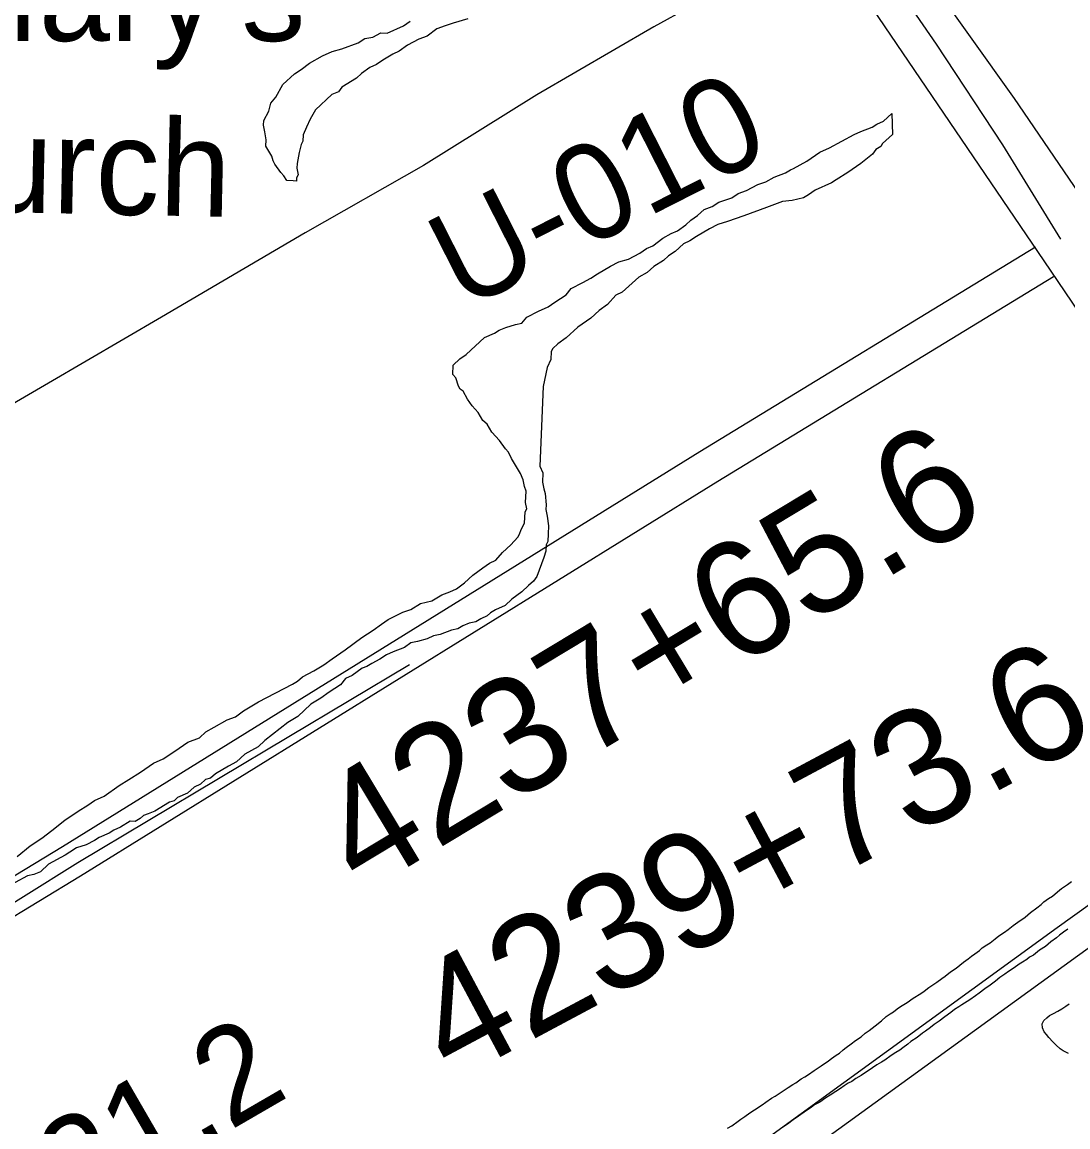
# Model space of a CAD drawing. Extents: x 3297753 to 3335611, y 652252 to 677623.
# Drawn here: x 3307391 to 3308297, y 669630 to 670586 of the extents above; entities that cross this region are included whole.
import ezdxf

# ---------------------------------------------------------------- set-up
doc = ezdxf.new("R2010")
doc.units = 0
for name, color, linetype in [('V-DTCH-CNTR', 7, 'Continuous'), ('V-LEVE-TOET', 7, 'Continuous'), ('V-RIVR-EDGE', 7, 'Continuous'), ('V-RIVR-RANG-IDEN', 7, 'Continuous'), ('V-ROAD-CNTR', 7, 'Continuous'), ('V-SITE-OTLN-IDEN', 7, 'Continuous'), ('V-SITE-VEGE', 7, 'Continuous'), ('V-SURV-IDEN', 7, 'Continuous'), ('V-TOPO-SHOR', 7, 'Continuous')]:
    doc.layers.add(name, color=color, linetype=linetype)

msp = doc.modelspace()

# ---------------------------------------------------------------- linework, layer by layer
at = {"layer": 'V-DTCH-CNTR'}
msp.add_lwpolyline([(3306851.89, 669500.8), (3306913.26, 669538.63), (3307005.87, 669594.48), (3307103.25, 669652.46), (3307138.08, 669673.72), (3307161.6, 669688.08), (3307298.09, 669770.19), (3307439.54, 669858.54), (3307622.29, 669967.41), (3307726.89, 670029.78)], dxfattribs=at)
at = {"layer": 'V-LEVE-TOET'}
msp.add_lwpolyline([(3308133.21, 670684.14), (3308250.51, 670519.66), (3308374.97, 670337.24), (3308533.16, 670097.88), (3308603.72, 669995.31), (3308676.85, 669890.86), (3308746.98, 669798.88), (3308783.09, 669756.81), (3308822.07, 669719.91), (3308908.96, 669649.25), (3309055.84, 669538.15), (3309202.86, 669430.58), (3309382.89, 669290.76), (3309531.09, 669190.18), (3309660.89, 669092.14), (3309690.67, 669067.09), (3309712.65, 669045.01), (3309817.76, 668967.41), (3309910.78, 668895.61), (3309933.41, 668877.39), (3310042.12, 668792.22), (3310236.32, 668633.29)], dxfattribs=at)
at = {"layer": 'V-RIVR-EDGE'}
msp.add_spline([(3307850.62, 675821), (3307850.75, 675819.26), (3307852.36, 675798.53), (3307852.34, 675791.07), (3307856.9, 675791.47), (3307860.2, 675784), (3307858.08, 675766.6), (3307858.03, 675745.87), (3307859.68, 675743.8), (3307863.41, 675742.96), (3307863.4, 675739.64), (3307862.94, 675720.99), (3307866.19, 675694.04), (3307864.47, 675668.35), (3307864.85, 675653.43), (3307866.04, 675632.29), (3307865.98, 675608.25), (3307860.93, 675578), (3307855.03, 675536.15), (3307852.01, 675490.98), (3307848.61, 675457.42), (3307845.62, 675420.95), (3307843.09, 675401.89), (3307841.81, 675387.8), (3307842.17, 675364.59), (3307841.69, 675337.23), (3307844.13, 675320.65), (3307845.74, 675299.92), (3307848.96, 675263.02), (3307851.37, 675230.27), (3307851.72, 675204.99), (3307854.14, 675179.28), (3307856.98, 675153.99), (3307856.53, 675138.24), (3307855.69, 675135.76), (3307856.07, 675118.35), (3307855.63, 675111.72), (3307854.35, 675095.97), (3307852.65, 675077.74), (3307852.18, 675054.11), (3307855.44, 675031.72), (3307862.38, 674991.5), (3307864.8, 674962.48), (3307868.44, 674926), (3307870.05, 674906.1), (3307872.46, 674875.01), (3307874.08, 674859.25), (3307876.52, 674843.5), (3307878.94, 674816.13), (3307882.53, 674757.68), (3307886.15, 674712.5), (3307885.71, 674704.21), (3307884.45, 674697.99), (3307884.44, 674691.78), (3307887.31, 674680.16), (3307887.28, 674668.97), (3307887.26, 674658.2), (3307885.58, 674651.15), (3307881.01, 674644.12), (3307881, 674639.97), (3307886.35, 674626.28), (3307890.03, 674605.55), (3307895.77, 674578.59), (3307899.43, 674550.81), (3307909.27, 674510.58), (3307914.59, 674481.97), (3307918.25, 674453.78), (3307918.22, 674440.51), (3307919.86, 674433.88), (3307927.3, 674423.08), (3307927.28, 674417.7), (3307927.25, 674404.02), (3307928.48, 674400.28), (3307931.78, 674393.23), (3307935.06, 674376.64), (3307944.54, 674357.55), (3307954.85, 674337.22), (3307963.92, 674316.06), (3307975.42, 674271.68), (3307986.49, 674225.23), (3308000.06, 674178.77), (3308007.44, 674148.91), (3308015.22, 674108.27), (3308020.53, 674078.42), (3308024.25, 674072.19), (3308025.04, 674059.34), (3308025.41, 674039.44), (3308027.79, 673997.16), (3308030.63, 673971.46), (3308027.69, 673955.3), (3308027.24, 673943.28), (3308027.64, 673935.82), (3308029.69, 673925.45), (3308035.46, 673911.76), (3308035.42, 673899.32), (3308034.12, 673873.21), (3308036.13, 673851.24), (3308038.54, 673818.91), (3308040.98, 673799), (3308046.76, 673788.21), (3308050.46, 673778.26), (3308048.79, 673772.46), (3308048.76, 673761.27), (3308053.68, 673740.53), (3308060.66, 673711.09), (3308069.7, 673678.73), (3308069.66, 673665.06), (3308067.15, 673653.46), (3308067.55, 673650.14), (3308072.94, 673649.3), (3308077.91, 673648.87), (3308079.98, 673646.38), (3308086.52, 673608.64), (3308091.84, 673582.1), (3308104.58, 673536.48), (3308114.83, 673495), (3308121.38, 673461), (3308123.83, 673446.07), (3308127.95, 673436.12), (3308140.31, 673406.24), (3308148.95, 673377.21), (3308153.04, 673357.72), (3308158.34, 673321.23), (3308169, 673273.12), (3308189.1, 673188.1), (3308196.88, 673150.37), (3308207.96, 673103.92), (3308212.04, 673079.45), (3308214.06, 673059.97), (3308216.51, 673045.04), (3308218.98, 673035.91), (3308226, 673025.53), (3308228.46, 673015.99), (3308228.43, 673002.32), (3308230.49, 672996.92), (3308235.04, 672992.77), (3308235.02, 672984.48), (3308237.47, 672972.87), (3308241.99, 672953.37), (3308247.32, 672933.05), (3308253.9, 672910.65), (3308257.61, 672901.53), (3308263.8, 672890.32), (3308276.17, 672865), (3308277.39, 672856.3), (3308278.62, 672850.08), (3308283.16, 672844.26), (3308286.05, 672839.7), (3308286.04, 672832.24), (3308285.59, 672818.97), (3308288.47, 672812.33), (3308293.83, 672800.3), (3308303.72, 672777.89), (3308309.9, 672762.54), (3308316.07, 672743.05), (3308316.44, 672725.64), (3308318.1, 672723.15), (3308323.06, 672717.33), (3308327.59, 672706.13), (3308331.69, 672690.37), (3308330.84, 672679.6), (3308330.4, 672672.14), (3308332.46, 672667.16), (3308337.42, 672658.44), (3308343.59, 672642.67), (3308347.7, 672625.26), (3308355.91, 672595.39), (3308355.89, 672584.62), (3308357.53, 672579.64), (3308362.07, 672570.92), (3308366.61, 672563.45), (3308376.07, 672534), (3308399.56, 672478.4), (3308411.51, 672452.67), (3308418.52, 672435.25), (3308421.79, 672418.66), (3308423.01, 672409.95), (3308425.49, 672403.73), (3308428.79, 672397.5), (3308430.01, 672387.55), (3308434.95, 672375.52), (3308444.41, 672344.83), (3308450.58, 672326.99), (3308456.78, 672320.76), (3308459.66, 672312.87), (3308465.4, 672287.99), (3308467.43, 672268.09), (3308473.18, 672249.01), (3308476.05, 672236.57), (3308485.95, 672214.16), (3308490.05, 672198.81), (3308495.86, 672201.7), (3308496.67, 672193), (3308499.08, 672161.9), (3308505.23, 672134.53), (3308513.87, 672107.57), (3308522.52, 672084.75), (3308527.9, 672082.25), (3308536.2, 672087.2), (3308540.76, 672086.78), (3308539.51, 672083.88), (3308535.76, 672077.67), (3308534.91, 672067.73), (3308534.47, 672059.44), (3308531.96, 672050.74), (3308533.2, 672047.42), (3308536.91, 672037.88), (3308550.93, 672008.42), (3308564.93, 671974.39), (3308569.87, 671959.46), (3308576.49, 671954.88), (3308585.14, 671932.48), (3308595.86, 671910.49), (3308604.94, 671895.13), (3308605.76, 671888.49), (3308607.82, 671885.17), (3308610.71, 671881.02), (3308616.47, 671862.77), (3308627.6, 671838.7), (3308640.39, 671816.29), (3308660.99, 671765.26), (3308672.95, 671740.77), (3308685.32, 671715.46), (3308698.53, 671692.21), (3308700.17, 671685.58), (3308711.29, 671658.19), (3308728.21, 671627.9), (3308743.07, 671602.99), (3308758.34, 671575.6), (3308771.97, 671554.84), (3308775.27, 671548.61), (3308783.11, 671536.16), (3308790.54, 671522.88), (3308793.43, 671519.55), (3308797.16, 671517.06), (3308801.29, 671511.24), (3308803.76, 671502.95), (3308810.8, 671502.1), (3308815.77, 671499.19), (3308833.53, 671474.28), (3308845.09, 671458.5), (3308857.08, 671443.55), (3308870.72, 671429.01), (3308882.71, 671418.61), (3308908.77, 671397), (3308930.27, 671375.39), (3308944.33, 671361.26), (3308952.58, 671346.74), (3308960.43, 671336.77), (3308966.22, 671331.78), (3308972.85, 671328.86), (3308985.64, 671307.28), (3309001.75, 671282.37), (3309010.84, 671271.57), (3309010.83, 671268.25), (3309008.34, 671266.19), (3309011.64, 671262.03), (3309018.66, 671250.83), (3309024.85, 671237.13), (3309035.15, 671212.24), (3309059.5, 671169.07), (3309066.5, 671150.82), (3309067.71, 671140.45), (3309071.85, 671135.88), (3309077.22, 671128.41), (3309078.45, 671123.02), (3309078.43, 671117.63), (3309082.15, 671111.4), (3309089.15, 671092.73), (3309098.63, 671073.23), (3309111.41, 671045.01), (3309116.36, 671032.15), (3309123.35, 671011), (3309128.7, 670995.65), (3309133.23, 670984.86), (3309143.97, 670967.42), (3309159.66, 670945.42), (3309169.17, 670933.37), (3309181.99, 670924.22), (3309188.19, 670917.16), (3309197.69, 670902.22), (3309217.1, 670874.81), (3309231.57, 670859.03), (3309239.82, 670845.33), (3309244.79, 670840.76), (3309252.23, 670835.35), (3309260.51, 670831.18), (3309275.4, 670817.06), (3309282.43, 670810.41), (3309290.69, 670800.02), (3309303.1, 670788.39), (3309315.92, 670775.51), (3309335.34, 670751), (3309344.42, 670736.47), (3309351.03, 670726.51), (3309360.13, 670721.51), (3309375.84, 670704.9), (3309390.72, 670688.69), (3309403.11, 670668.77), (3309415.49, 670646.77), (3309426.65, 670635.14), (3309442.78, 670618.52), (3309454.34, 670603.15), (3309462.18, 670588.63), (3309470.85, 670575.34), (3309476.63, 670563.31), (3309487.39, 670558.31), (3309488.62, 670554.57), (3309489.44, 670550.84), (3309494.82, 670544.2), (3309506.81, 670533.39), (3309523.77, 670518.84), (3309529.95, 670505.98), (3309538.6, 670484.82), (3309549.72, 670453.7), (3309551.35, 670440.85), (3309555.47, 670430.89), (3309568.67, 670408.89), (3309577.35, 670396.02), (3309581.47, 670386.48), (3309581.46, 670383.16), (3309578.55, 670379.85), (3309576.88, 670374.88), (3309582.24, 670364.09), (3309594.61, 670336.71), (3309604.49, 670308.91), (3309606.94, 670296.06), (3309614.38, 670284.85), (3309627.18, 670266.99), (3309635.46, 670261.59), (3309639.18, 670259.92), (3309638.74, 670249.97), (3309639.54, 670236.29), (3309641.18, 670228), (3309644.89, 670221.36), (3309656.46, 670208.06), (3309664.31, 670195.61), (3309663.46, 670188.15), (3309663.84, 670176.13), (3309667.96, 670166.17), (3309673.34, 670159.94), (3309684.07, 670142.92), (3309690.66, 670126.33), (3309700.14, 670102.68), (3309716.65, 670076.52)], degree=3, dxfattribs=at)
at = {"layer": 'V-ROAD-CNTR'}
for points in [[(3307339.14, 672310.87), (3307407.41, 672029.86), (3307476.95, 671732.57), (3307511.07, 671600.1), (3307529.82, 671540.23), (3307554.17, 671481.54), (3307565.65, 671454.66), (3307628.51, 671339.43), (3307687.48, 671244.51), (3307819.52, 671049.73), (3308010.54, 670769.93), (3308276.08, 670379.16), (3308519.64, 670019.78), (3308575.25, 669936.41), (3308626.7, 669864.47), (3308662.44, 669815.55), (3308701.66, 669766.43), (3308749.57, 669726.83), (3308879.73, 669615.8), (3309312.15, 669283.51), (3309781.29, 668929.63), (3310172.08, 668625.19)], [(3308268.94, 670390.98), (3307978.15, 670213.72), (3307426.28, 669872.11), (3306771.84, 669474.94)], [(3308284.55, 670365.37), (3307993.85, 670188.16), (3307441.96, 669846.54), (3306828.11, 669473.99)], [(3308552.14, 669971.42), (3308505.63, 669941.31), (3308470.59, 669919.23), (3308429.58, 669897.99), (3308390.61, 669875.75), (3308287.73, 669801.85), (3307991.97, 669587.42), (3307744.65, 669410.84)], [(3308568.45, 669946.24), (3308521.78, 669916.02), (3308485.5, 669893.17), (3308443.92, 669871.63), (3308406.84, 669850.47), (3308305.29, 669777.52), (3308009.49, 669563.07), (3307762.08, 669386.42)]]:
    msp.add_lwpolyline(points, dxfattribs=at)
at = {"layer": 'V-SITE-VEGE'}
for points in [[(3307777.26, 670588.54), (3307764.66, 670584.92), (3307757.64, 670582.45), (3307750.62, 670579.98), (3307742.04, 670573.43), (3307735.03, 670570.96), (3307725.13, 670565.85), (3307717.99, 670560.62), (3307712.35, 670558.09), (3307703.84, 670552.92), (3307698.14, 670549.01), (3307692.5, 670546.48), (3307685.36, 670541.26), (3307681.04, 670537.29), (3307668.27, 670529.53), (3307665.33, 670525.51), (3307659.69, 670522.98), (3307645.3, 670509.76), (3307640.81, 670501.65), (3307637.75, 670494.86), (3307634.7, 670488.08), (3307634.47, 670482.56), (3307632.97, 670479.86), (3307631.3, 670473.01), (3307629.51, 670463.41), (3307629.33, 670459.26), (3307630.48, 670453.69), (3307628.98, 670450.98), (3307628.87, 670448.22), (3307626.11, 670448.34), (3307620.58, 670448.57), (3307618, 670452.83), (3307615.35, 670455.71), (3307610.12, 670462.84), (3307608.86, 670465.66), (3307607.65, 670469.86), (3307602.48, 670478.38), (3307602.72, 670483.9), (3307601.63, 670490.87), (3307600.48, 670496.45), (3307600.66, 670500.59), (3307605.15, 670508.7), (3307606.82, 670515.54), (3307611.2, 670520.89), (3307617.19, 670531.7), (3307627.26, 670540.95), (3307632.96, 670544.86), (3307640.1, 670550.09), (3307651.43, 670556.53), (3307659.89, 670560.32), (3307668.29, 670562.73), (3307682.33, 670567.66), (3307688.03, 670571.57), (3307694.99, 670572.66), (3307702.07, 670576.51), (3307707.59, 670576.28), (3307721.69, 670582.59), (3307727.39, 670586.5)], [(3308117.52, 670491.14), (3308127.36, 670494.87), (3308131.62, 670497.45), (3308137.25, 670499.98), (3308144.45, 670506.59), (3308145.07, 670488.58), (3308142.19, 670485.94), (3308136.44, 670480.65), (3308134.94, 670477.95), (3308130.68, 670475.36), (3308127.74, 670471.34), (3308117.72, 670463.47), (3308106.33, 670455.65), (3308096.38, 670449.16), (3308092.12, 670446.57), (3308078.02, 670440.26), (3308072.32, 670436.35), (3308068.06, 670433.76), (3308058.28, 670431.41), (3308049.94, 670430.38), (3308035.9, 670425.44), (3308016.22, 670417.98), (3308002.18, 670413.04), (3307993.78, 670410.63), (3307986.7, 670406.78), (3307975.37, 670400.34), (3307969.67, 670396.44), (3307964.03, 670393.91), (3307956.83, 670387.3), (3307951.13, 670383.39), (3307946.82, 670379.43), (3307938.3, 670374.26), (3307932.54, 670368.97)], [(3307576.02, 669984.37), (3307583.16, 669989.6), (3307595.93, 669997.36), (3307625.62, 670012.7), (3307629.88, 670015.28), (3307634.2, 670019.25), (3307644.1, 670024.36), (3307652.61, 670029.53), (3307659.75, 670034.76), (3307671.15, 670042.58), (3307685.42, 670053.04), (3307695.38, 670059.53), (3307702.52, 670064.76), (3307708.21, 670068.67), (3307720.93, 670075.05), (3307727.95, 670077.51), (3307736.47, 670082.68), (3307746.25, 670085.04), (3307754.77, 670090.21), (3307761.79, 670092.67), (3307767.43, 670095.2), (3307774.56, 670100.43), (3307781.76, 670107.05), (3307790.33, 670113.59), (3307796.03, 670117.5), (3307801.67, 670120.03), (3307807.48, 670126.7), (3307814.68, 670133.31), (3307820.5, 670139.98), (3307821.99, 670142.68), (3307823.55, 670146.76), (3307826.54, 670152.17), (3307826.95, 670161.83), (3307828.45, 670164.54), (3307827.31, 670170.12), (3307827.71, 670179.78), (3307826.51, 670183.98), (3307825.36, 670189.57), (3307822.83, 670195.2), (3307815.08, 670207.98), (3307812.55, 670213.62), (3307809.91, 670216.49), (3307804.68, 670223.63), (3307798.07, 670230.83), (3307794.22, 670237.91), (3307790.19, 670240.84), (3307786.34, 670247.92), (3307781.06, 670253.68), (3307777.15, 670259.38), (3307773.3, 670266.45), (3307770.6, 670267.95), (3307769.33, 670270.77), (3307766.86, 670277.79), (3307764.22, 670280.67), (3307764.57, 670288.95), (3307770.33, 670294.24), (3307776.02, 670298.15), (3307791.85, 670312.69), (3307800.31, 670316.48), (3307804.57, 670319.07), (3307810.21, 670321.59), (3307818.61, 670324), (3307824.19, 670325.15), (3307828.57, 670330.5), (3307838.46, 670335.61), (3307846.93, 670339.4), (3307852.62, 670343.31), (3307862.58, 670349.8), (3307866.96, 670355.15), (3307876.85, 670360.26), (3307883.93, 670364.11), (3307889.63, 670368.02), (3307900.97, 670374.45), (3307908.04, 670378.3), (3307916.45, 670380.71), (3307926.34, 670385.83), (3307932.04, 670389.73), (3307937.68, 670392.26), (3307946.25, 670398.82), (3307953.33, 670402.66), (3307958.97, 670405.19), (3307966.11, 670410.42), (3307970.43, 670414.39), (3307976.12, 670418.29), (3307981.88, 670423.58), (3307988.9, 670426.05), (3307994.6, 670429.96), (3308005.82, 670433.63), (3308011.52, 670437.54), (3308018.54, 670440.01), (3308028.44, 670445.12), (3308035.45, 670447.59), (3308042.53, 670451.44), (3308052.37, 670455.17), (3308056.63, 670457.76), (3308059.45, 670459.02), (3308070.79, 670465.45), (3308082.18, 670473.27), (3308090.64, 670477.06), (3308111.88, 670488.61), (3308117.52, 670491.14)], [(3307932.54, 670368.97), (3307925.46, 670365.11), (3307911.08, 670351.9), (3307905.44, 670349.37), (3307898.18, 670341.38), (3307891.04, 670336.15), (3307883.85, 670329.54), (3307872.45, 670321.72), (3307862.38, 670312.47), (3307855.24, 670307.24), (3307850.93, 670303.27), (3307849.43, 670300.57), (3307849.14, 670293.67), (3307846.08, 670286.88), (3307842.62, 670270.43), (3307839.7, 670201.4), (3307842.22, 670195.76), (3307841.87, 670187.48), (3307843.02, 670181.9), (3307844.22, 670177.7), (3307845.2, 670167.97), (3307845.02, 670163.84), (3307846.17, 670158.25), (3307847.2, 670149.91), (3307846.9, 670143.01), (3307846.61, 670136.11), (3307845.11, 670133.4), (3307844.88, 670127.88), (3307843.26, 670122.42), (3307837.04, 670106.08), (3307834.1, 670102.06), (3307829.79, 670098.09), (3307824.03, 670092.81), (3307815.45, 670086.25), (3307809.7, 670080.97), (3307801.24, 670077.18), (3307796.98, 670074.59), (3307794.1, 670071.94), (3307788.46, 670069.42), (3307784.2, 670066.83), (3307778.62, 670065.69), (3307772.98, 670063.16), (3307768.73, 670060.57), (3307763.14, 670059.43), (3307753.3, 670055.69), (3307747.72, 670054.55), (3307742.08, 670052.02), (3307733.68, 670049.61), (3307728.1, 670048.46), (3307722.41, 670044.55), (3307712.57, 670040.82), (3307706.93, 670038.3), (3307701.23, 670034.39), (3307694.15, 670030.54), (3307689.89, 670027.95), (3307685.69, 670026.75), (3307677.12, 670020.2), (3307671.48, 670017.67), (3307667.1, 670012.32), (3307657.14, 670005.83), (3307650.01, 670000.6), (3307641.49, 669995.43), (3307629.98, 669984.85), (3307621.46, 669979.68), (3307601.43, 669963.93), (3307595.67, 669958.64), (3307584.34, 669952.21), (3307577.14, 669945.6), (3307570.06, 669941.75), (3307558.73, 669935.31), (3307554.41, 669931.34), (3307550.21, 669930.14), (3307545.89, 669926.18), (3307540.25, 669923.65), (3307534.5, 669918.36), (3307526.04, 669914.57), (3307523.16, 669911.93), (3307518.96, 669910.72), (3307506.18, 669902.96), (3307500.54, 669900.44), (3307496.34, 669899.23), (3307493.46, 669896.59), (3307489.21, 669894), (3307485.06, 669894.18), (3307476.55, 669889.01), (3307470.91, 669886.48), (3307466.65, 669883.89), (3307458.19, 669880.1), (3307453.93, 669877.52), (3307446.85, 669873.67), (3307438.45, 669871.26), (3307432.75, 669867.35), (3307428.5, 669864.76), (3307414.34, 669857.06), (3307407.14, 669850.45), (3307401.5, 669847.93), (3307395.92, 669846.78), (3307374.69, 669835.23)], [(3307386.96, 669863.76), (3307398.42, 669872.95), (3307408.37, 669879.45), (3307416.95, 669886), (3307428.4, 669895.19), (3307439.8, 669903.01), (3307448.31, 669908.18), (3307454.01, 669912.09), (3307462.47, 669915.88), (3307475.31, 669925.02), (3307483.82, 669930.19), (3307493.78, 669936.68), (3307505.18, 669944.5), (3307513.64, 669948.29), (3307523.59, 669954.78), (3307534.99, 669962.6), (3307544.83, 669966.33), (3307550.58, 669971.62), (3307557.66, 669975.47), (3307569, 669981.9), (3307576.02, 669984.37)]]:
    msp.add_lwpolyline(points, dxfattribs=at)
at = {"layer": 'V-TOPO-SHOR'}
for points in [[(3307501.52, 671756.93), (3307522.84, 671670.87), (3307549.05, 671573.34), (3307570.79, 671508.8), (3307596.66, 671449.46), (3307620.56, 671401.47), (3307651.16, 671349.76), (3307683.37, 671301.41), (3307737.05, 671216.92), (3307790.17, 671142.23), (3307815.79, 671100.03), (3307872.61, 671020.3), (3307947.88, 670913.84), (3308010.85, 670817.7), (3308070.34, 670731.49), (3308118.69, 670659.94), (3308182.77, 670566.68), (3308240.26, 670479.58), (3308290.54, 670397.97)], [(3308064.15, 670651.31), (3307938.5, 670581.74), (3307837.19, 670522.69), (3307738.98, 670461.51), (3307636.52, 670403.3), (3307511.92, 670330.49), (3307414.28, 670273.28), (3307301.14, 670207.56), (3307176.53, 670134.35), (3307081.62, 670075.82), (3306992.78, 670019.43), (3306956.52, 670000.65)], [(3308002.28, 669628.44), (3308005.89, 669630.63), (3308011.33, 669634.5), (3308013.75, 669636.45), (3308017.07, 669638.65), (3308021.6, 669641.68), (3308025.52, 669644.45), (3308032.16, 669648.85), (3308035.47, 669651.06), (3308040.3, 669654.36), (3308043.6, 669656.28), (3308047.82, 669659.03), (3308050.54, 669660.96), (3308054.76, 669663.71), (3308058.67, 669666.19), (3308061.38, 669667.83), (3308065.91, 669671.15), (3308069.22, 669673.06), (3308072.23, 669674.99), (3308077.36, 669678.58), (3308083.38, 669682.43), (3308089.72, 669686.84), (3308092.15, 669688.79), (3308096.38, 669691.83), (3308099.09, 669693.48), (3308102.43, 669696.27), (3308104.85, 669698.21), (3308109.39, 669701.54), (3308113.02, 669704.32), (3308117.85, 669707.63), (3308121.5, 669710.7), (3308124.83, 669713.19), (3308129.97, 669717.08), (3308135.43, 669721.53), (3308139.69, 669725.16), (3308143.01, 669727.36), (3308146.02, 669729.29), (3308149.06, 669731.79), (3308152.06, 669733.72), (3308157.78, 669737.29), (3308162.93, 669741.17), (3308169.54, 669744.99), (3308172.56, 669747.2), (3308176.5, 669750.26), (3308179.2, 669751.91), (3308183.43, 669754.95), (3308187.67, 669757.99), (3308190.69, 669760.21), (3308195.24, 669763.83), (3308200.07, 669767.13), (3308203.39, 669769.63), (3308206.43, 669772.14), (3308210.66, 669775.18), (3308213.39, 669777.41), (3308216.4, 669779.33), (3308220.34, 669782.39), (3308222.78, 669784.63), (3308226.69, 669787.1), (3308229.71, 669789.03), (3308233.95, 669792.36), (3308237.28, 669794.86), (3308242.1, 669798.17), (3308245.13, 669800.38), (3308249.68, 669804), (3308253.6, 669806.76), (3308259.94, 669811.18), (3308264.5, 669815.09), (3308269.95, 669819.26), (3308273.88, 669822.02), (3308276.03, 669824.27), (3308280.26, 669827.32), (3308283.56, 669829.23), (3308287.83, 669833.15), (3308291.46, 669835.93), (3308296.59, 669839.52), (3308300.21, 669842)], [(3308297.01, 669800.82), (3308293.08, 669798.06), (3308289.75, 669795.57), (3308287.02, 669793.34), (3308282.18, 669789.73), (3308277.62, 669785.82), (3308272.5, 669782.53), (3308267.05, 669778.36), (3308263.75, 669776.45), (3308261.32, 669774.5), (3308257.71, 669772.31), (3308254.7, 669770.39), (3308250.47, 669767.34), (3308245.64, 669764.03), (3308242.33, 669761.83), (3308238.09, 669758.79), (3308234.16, 669755.73), (3308229.62, 669752.41), (3308225.08, 669749.08), (3308220.24, 669745.48), (3308216.92, 669742.98), (3308212.09, 669739.67), (3308205.16, 669735.28), (3308202.45, 669733.63), (3308198.83, 669731.15), (3308195.5, 669728.65), (3308190.36, 669724.77), (3308185.52, 669721.17), (3308181.29, 669718.12), (3308177.96, 669715.63), (3308173.73, 669712.58), (3308171.01, 669710.65), (3308166.46, 669707.03), (3308161.04, 669703.45), (3308158.31, 669701.23), (3308154.07, 669698.18), (3308151.34, 669695.95), (3308148.04, 669694.04), (3308143.82, 669691.29), (3308138.38, 669687.42), (3308135.68, 669685.78), (3308131.47, 669683.32), (3308127.85, 669680.83), (3308123.93, 669678.07), (3308120.91, 669676.15), (3308117.9, 669674.22), (3308113.39, 669671.49), (3308109.77, 669669), (3308106.77, 669667.37)], [(3308297.5, 669693.08), (3308292.75, 669695.58), (3308290.29, 669697.31), (3308286.72, 669700.46), (3308283.84, 669703.36), (3308280.53, 669706.97), (3308278.56, 669709.59), (3308276.35, 669712), (3308275.1, 669715.28), (3308274.56, 669718.78), (3308276.06, 669721.71), (3308278.71, 669724.15), (3308281.1, 669726.12), (3308284.64, 669727.82), (3308288.19, 669729.75), (3308291.74, 669731.68), (3308295.31, 669734.07), (3308298.17, 669736.26)], [(3308106.77, 669667.37), (3308103.16, 669665.18), (3308100.14, 669662.96), (3308095.92, 669660.21), (3308091.1, 669657.2), (3308087.48, 669654.71), (3308082.06, 669651.13), (3308077.56, 669648.69), (3308074.84, 669646.75), (3308072.12, 669644.81), (3308068.5, 669642.33), (3308063.67, 669639.02), (3308059.14, 669635.7), (3308055.21, 669632.93), (3308050.68, 669629.61)]]:
    msp.add_lwpolyline(points, dxfattribs=at)

# ---------------------------------------------------------------- texts
at = {"layer": 'V-RIVR-RANG-IDEN'}
for s, rotation, p in [('U-010', 26.92151, (3307773.05, 670335.49)), ('R-221.2', 30.09311, (3307282.91, 669459.1))]:
    msp.add_text(s, height=83, rotation=rotation, dxfattribs=at).set_placement(p)
at = {"layer": 'V-SITE-OTLN-IDEN'}
msp.add_text("St.Mary's", height=83, dxfattribs=at).set_placement((3307177.71, 670569.48))
msp.add_text('Church', height=83, rotation=358.78183, dxfattribs=at).set_placement((3307213.67, 670424.69))
at = {"layer": 'V-SURV-IDEN'}
for s, rotation, p in [('4237+65.6', 31.07028, (3307686.22, 669830.74)), ('4239+73.6', 28.1246, (3307764.44, 669668.13))]:
    msp.add_text(s, height=100, rotation=rotation, dxfattribs=at).set_placement(p)

doc.saveas('drawing.dxf')
